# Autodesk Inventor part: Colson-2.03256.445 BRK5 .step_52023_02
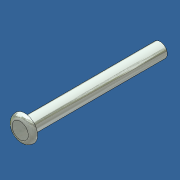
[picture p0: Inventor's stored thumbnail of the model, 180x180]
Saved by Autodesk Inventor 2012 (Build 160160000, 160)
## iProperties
Created: 2010-10
Part Number: Colson-2.03256.445 BRK5 .step_52023_02
Document SubType Name: Modeling
Designer: Administrator
Density: 7.85 g/cm^3
Material: Steel
Mass: 6.19676 g
Surface Area: 8.22046 cm^2
Volume: 0.789396 cm^3
Author: Administrator
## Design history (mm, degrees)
feature "Base1"
body "Solid1"
